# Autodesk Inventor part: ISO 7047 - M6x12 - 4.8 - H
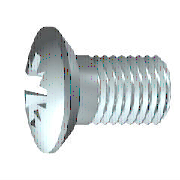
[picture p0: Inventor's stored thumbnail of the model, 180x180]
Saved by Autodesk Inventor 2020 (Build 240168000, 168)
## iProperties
Created: 2019-01
Part Number: ISO 7047 - M6x12 - 4.8 - H
Material: Acier
Description: Vis à tête fraisée bombée (type de tête standard) avec empreinte cruciforme de type H ou Z. Produit de classe A
Document SubType Name: Modeling
Standard: ISO 7047 (H)
Designer: %USERNAME%
Standard Revision: Third edition 2011-09-01
Standards Organization: ISO
Language: fr-FR
Size Designation: M6x12 - 4.8 - H
Categories: <MemberInstance><Categories><Category DisplayName="Visserie" InternalName="e4da775c-781d-43d5-af7c-5136215cf5a6" Mnemonic="FSTN"><Category DisplayName="Vis" Int
Density: 7.85 g/cm^3
Appearance: Plaque
IsCustomPart: 0
Author: %USERNAME%
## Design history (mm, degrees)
node "WorkPlane2"
node "WorkPoint1"
workplane "Work Plane2"
node "WorkPlane3"
node "WorkPoint2"
pattern_circular "RéseauPolaire1" dims angle "d38" = 360 deg
node "MSC_A1"
node "MSC_PF1"
node "MSC_PT1"
body "Solid1"
node "Esquisse1"
node "Esquisse2"
sketch "Esquisse3"
  geometry: L1 (3, -6.7)-(2.5, -5.7); L2 (3, -13.4)-(3, -6.7); L3 (0, -13.4)-(3, -13.4); L4 (0, 0)-(0, -13.4); L5 (5.65, -1.55)-(5.65, -1.4); L6 (2.5, -4.7)-(5.65, -1.55); L7 (2.5, -5.7)-(2.5, -4.7); L8 (0, -31.645)-(0, 31.645); L9 (0, -31.645)-(0, 31.645); L10 (0, -44.302)-(0, 44.302) reference; A1 r 12.101 centre (0, -12.101) between (5.65, -1.4) and (0, 0); 1 further point
  constraints: 18 end point, 5 vertical, 2 midpoint, 2 point on circle, 1 centre point, 1 collinear, 1 horizontal
  dimensions: "d2" = 3 distance of L3.start L2.start (= 0.5 x NND); "d4" = 2.5 horizontal distance of L6.start L4.start (= 0.5 x msp_mdtds); "d6" = 1 vertical distance of L1.start L1.end (= msp_x); "d8" = 3.3 vertical distance of L5.end L6.start (= ParK); "d10" = 135 deg angle of L7 L6; "d12" = 5.65 horizontal distance of L5.end L4.start (= 0.5 x Dk); "d14" = 0 horizontal distance of A1.centre L4.start; "d16" = 1.4 vertical distance of L5.end L4.start (= ParF); "d18" = 12 vertical distance of L5.end L3.start (= NLG); "d22" = 6.7 distance of L2.start L1.start (= b)
revolve "Révolution1" stored, may be unused: angle "d23" = 360 deg
fillet "Congé1" dims "d24" = 1.5 (= r)
sketch "Esquisse4"
  geometry: L1 (0, 0)-(-3.65, 0); L2 (0, -3.042)-(0, 0); L3 (-3.65, 0)-(-0.608, -3.042); L4 (0, -14.521)-(0, 2.42) reference; L5 (0, -3.042)-(-0.608, -3.042); A1 r 12.101 centre (0, -12.101) between (5.65, -1.4) and (-5.65, -1.4) reference; 1 further point
  constraints: 8 end point, 3 point on line, 1 horizontal, 1 tangent, 1 vertical
  dimensions: "d30" = 45 deg angle of L1 L3; "d33" = 7.3 diameter of L1.end L2 (= M); "d34" = 0.60833 distance of L2.start point (0, -3.65) (= 0.0833333 x M); "d35" = 90 deg angle of L2 L5
extrude "Extrusion1" cut sketch "Esquisse4" stored distance "d31" = 1.21667 (= 0.166667 x M); taper "d32" = 0 deg
feature "Filetage1" dims "d39" = 6.7 (= b), "d40" = 0
other parameters: "PTC" = 1 [user parameter; used in 2 equation terms], "msp_x" = 1 (= PTC) [user parameter; used in 1 equation term], "NLG" = 12 [user parameter; used in 1 equation term], "NND" = 6 [user parameter; used in 3 equation terms], "ParK" = 3.3 [user parameter; used in 2 equation terms], "r" = 1.5 [user parameter; used in 1 equation term], "msp_mdtds" = 5 (= NND - PTC) [user parameter; used in 1 equation term], "b" = 6.7 [user parameter; used in 2 equation terms], "Dk" = 11.3 [user parameter; used in 1 equation term], "ParF" = 1.4 [user parameter; used in 2 equation terms], "M" = 7.3 [user parameter; used in 3 equation terms], "ParA" = 2 [user parameter], "d0" = -4.7 (computed from ParK, ParF), "d1" = 5 (derived), "d3" = 4.5 (derived), "d5" = 1 (derived), "d7" = 5 (derived), "d9" = 135 deg (derived), "d11" = 9 (derived), "d13" = 0 (derived), "d15" = 2 (derived), "d19" = 0 (derived), "d21" = 15 (derived), "d25" = 4.16667 (derived), "d27" = 5 (derived), "d29" = 45 deg (derived), "d43" = 0, "d44" = 0, "d45" = 0, "d46" = 0, "THREADDIA" = 6 (= NND) [user parameter], "TEMPLATE" = 12.345 [user parameter]
